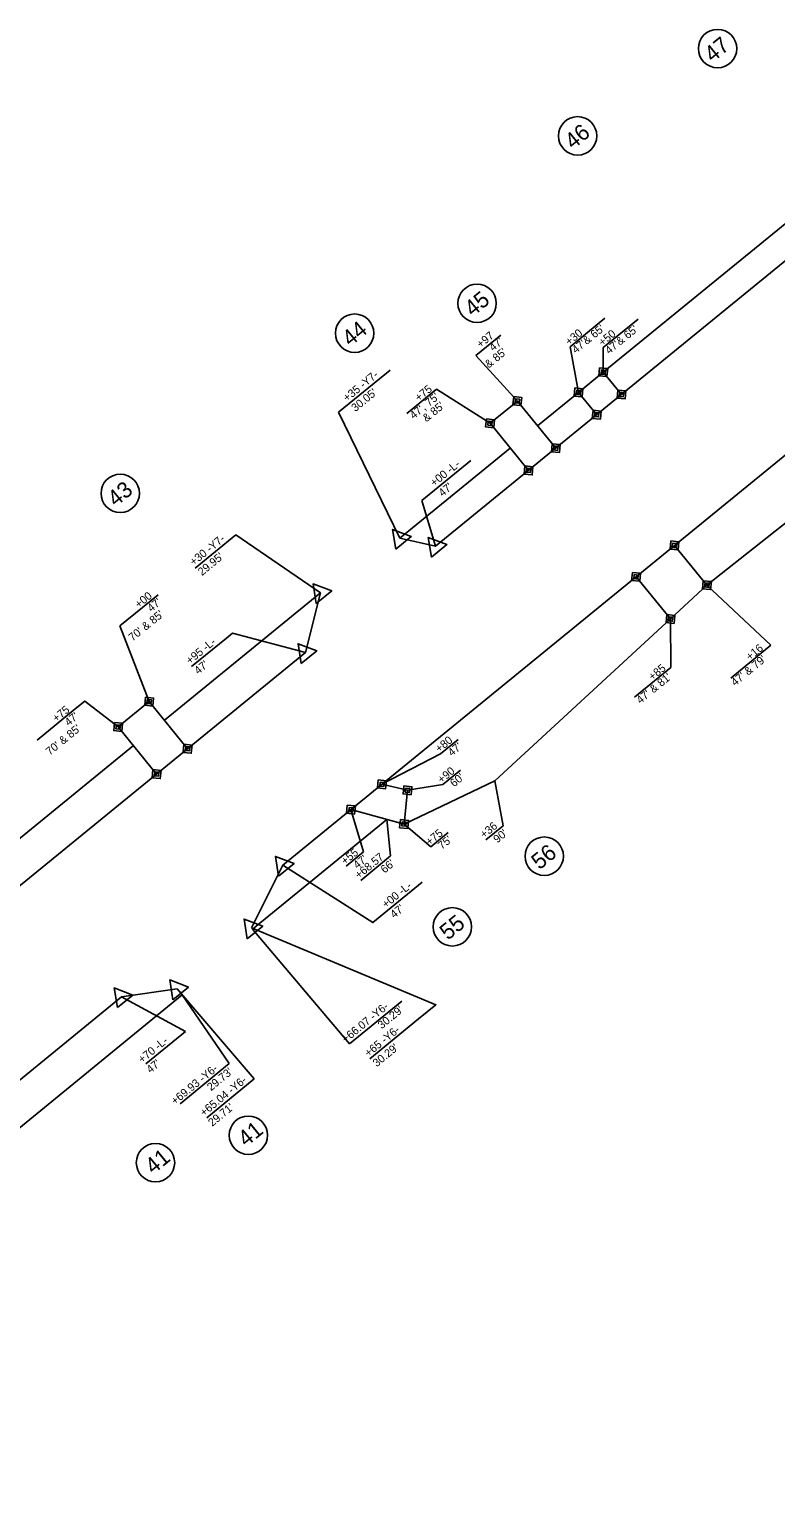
# Model space of a CAD drawing. Extents: x 2320946 to 2332748, y 597838 to 612698.
# Drawn here: x 2323481 to 2323947, y 599158 to 600075 of the extents above; entities that cross this region are included whole.
import ezdxf

# ---------------------------------------------------------------- set-up
doc = ezdxf.new("R2010")
doc.units = 0
for name, color, linetype in [('Prop Easement Construction', 7, 'Continuous'), ('Prop Easement Construction Station Offsets', 7, 'Continuous'), ('Prop Easement Permanent Drainage', 7, 'Continuous'), ('Prop Easement Permanent Drainage Station Offsets', 7, 'Continuous'), ('Prop Easement Permanent Utility', 7, 'Continuous'), ('Prop Easement Permanent Utility Station Offsets', 7, 'Continuous'), ('Prop Parcel Number CELL', 7, 'Continuous'), ('Prop ROW Marker CELL', 7, 'Continuous'), ('Prop ROW Permanent Easement CELL', 7, 'Continuous'), ('Prop ROW RW Lines', 7, 'Continuous'), ('Prop ROW Station Offsets', 7, 'Continuous')]:
    doc.layers.add(name, color=color, linetype=linetype)

msp = doc.modelspace()

# ---------------------------------------------------------------- linework, layer by layer
at = {"layer": 'Prop Easement Construction'}
for p, q in [((2323839.33, 599860.7), (2323982.64, 599977.7)), ((2323904.06, 599727.66), (2324067.08, 599856.87)), ((2323798.27, 599827.19), (2323823.84, 599848.06)), ((2323712.21, 599756.93), (2323781.23, 599813.27)), ((2323565.05, 599643.24), (2323662.58, 599722.86)), ((2323771.58, 599605.3), (2323881.31, 599706.5)), ((2323417.87, 599523.08), (2323545.68, 599627.42)), ((2323714.84, 599578.34), (2323771.58, 599605.3)), ((2323620.12, 599512.63), (2323704.17, 599581.25)), ((2323192.2, 599158.11), (2323576.17, 599471.58))]:
    msp.add_line(p, q, dxfattribs=at)
at = {"layer": 'Prop Easement Construction Station Offsets'}
for p, q in [((2323776.81, 599577.3), (2323765.91, 599568.41)), ((2323706.43, 599558.43), (2323687.77, 599543.19)), ((2323680.72, 599440.98), (2323620.12, 599512.63)), ((2323605.58, 599428.66), (2323576.17, 599471.58)), ((2323713.53, 599467.65), (2323680.72, 599440.98)), ((2323605.58, 599428.66), (2323574.96, 599403.66))]:
    msp.add_line(p, q, dxfattribs=at)
for points in [[(2323776.81, 599577.3), (2323771.58, 599605.3)], [(2323706.43, 599558.43), (2323704.17, 599581.25)]]:
    msp.add_lwpolyline(points, dxfattribs=at)
at = {"layer": 'Prop Easement Permanent Drainage'}
for p, q in [((2323823.84, 599848.06), (2323839.33, 599860.7)), ((2323850.71, 599846.76), (2323839.33, 599860.7)), ((2323835.22, 599834.11), (2323823.84, 599848.06))]:
    msp.add_line(p, q, dxfattribs=at)
at = {"layer": 'Prop Easement Permanent Drainage Station Offsets'}
for p, q in [((2323840.37, 599894.39), (2323818.55, 599876.58)), ((2323861.15, 599893.92), (2323839.33, 599876.11))]:
    msp.add_line(p, q, dxfattribs=at)
for points in [[(2323818.55, 599876.58), (2323823.84, 599848.06)], [(2323839.33, 599876.11), (2323839.33, 599860.7)]]:
    msp.add_lwpolyline(points, dxfattribs=at)
at = {"layer": 'Prop Easement Permanent Utility'}
for p, q in [((2323785.63, 599842.68), (2323768.58, 599828.77)), ((2323785.63, 599842.68), (2323809.66, 599813.24)), ((2323768.58, 599828.77), (2323792.62, 599799.33)), ((2323904.06, 599727.66), (2323883.82, 599752.44)), ((2323881.31, 599706.5), (2323859.81, 599732.84)), ((2323881.31, 599706.5), (2323904.06, 599727.66)), ((2323536.19, 599639.04), (2323555.56, 599654.85)), ((2323555.56, 599654.85), (2323579.59, 599625.42)), ((2323560.23, 599609.61), (2323536.19, 599639.04))]:
    msp.add_line(p, q, dxfattribs=at)
msp.add_lwpolyline([(2323681.64, 599587.39), (2323714.84, 599578.34), (2323716.98, 599599.45), (2323701.01, 599603.2)], dxfattribs=at)
at = {"layer": 'Prop Easement Permanent Utility Station Offsets'}
for p, q in [((2323775.21, 599883.81), (2323759.64, 599871.1)), ((2323785.63, 599842.68), (2323759.64, 599871.1)), ((2323735.13, 599850.07), (2323716.51, 599834.87)), ((2323735.13, 599850.07), (2323768.58, 599828.77)), ((2323944.08, 599690.04), (2323904.06, 599727.66)), ((2323561.09, 599721.61), (2323537.28, 599702.17)), ((2323881.58, 599676.22), (2323881.31, 599706.5)), ((2323944.08, 599690.04), (2323919.02, 599669.58)), ((2323881.58, 599676.22), (2323858.93, 599657.74)), ((2323509.36, 599650.27), (2323485.62, 599630.88)), ((2323748.61, 599631.26), (2323737.64, 599622.3)), ((2323750.01, 599611.99), (2323739.04, 599603.03)), ((2323742.42, 599572.99), (2323731.57, 599564.13)), ((2323689.56, 599560.93), (2323678.71, 599552.08))]:
    msp.add_line(p, q, dxfattribs=at)
for points in [[(2323537.28, 599702.17), (2323555.56, 599654.85)], [(2323509.36, 599650.27), (2323515.38, 599655.18), (2323536.19, 599639.04)], [(2323737.64, 599622.3), (2323701.01, 599603.2)], [(2323739.04, 599603.03), (2323716.98, 599599.45)], [(2323689.56, 599560.93), (2323681.64, 599587.39)], [(2323731.57, 599564.13), (2323714.84, 599578.34)]]:
    msp.add_lwpolyline(points, dxfattribs=at)
at = {"layer": 'Prop Parcel Number CELL'}
for p, q in [((2323910.72, 600062.92), (2323910.72, 600062.92)), ((2323823.3, 600008.37), (2323823.3, 600008.37)), ((2323760.49, 599903.76), (2323760.49, 599903.76)), ((2323683.95, 599885.07), (2323683.95, 599885.07)), ((2323537.47, 599784.98), (2323537.47, 599784.98)), ((2323802.42, 599558.29), (2323802.42, 599558.29)), ((2323745.01, 599514.15), (2323745.01, 599514.15)), ((2323617.55, 599383.94), (2323617.55, 599383.94)), ((2323559.52, 599366.78), (2323559.52, 599366.78))]:
    msp.add_line(p, q, dxfattribs=at)
for centre in [(2323910.72, 600062.92), (2323823.3, 600008.37), (2323760.49, 599903.76), (2323683.95, 599885.07), (2323537.47, 599784.98), (2323802.42, 599558.29), (2323745.01, 599514.15), (2323617.55, 599383.94), (2323559.52, 599366.78)]:
    msp.add_circle(centre, 12, dxfattribs=at)
at = {"layer": 'Prop ROW Marker CELL'}
for p, q in [((2323839.33, 599860.7), (2323839.33, 599860.7)), ((2323785.63, 599842.68), (2323785.63, 599842.68)), ((2323823.84, 599848.06), (2323823.84, 599848.06)), ((2323850.71, 599846.76), (2323850.71, 599846.76)), ((2323835.22, 599834.11), (2323835.22, 599834.11)), ((2323768.58, 599828.77), (2323768.58, 599828.77)), ((2323809.66, 599813.24), (2323809.66, 599813.24)), ((2323792.62, 599799.33), (2323792.62, 599799.33)), ((2323712.21, 599756.93), (2323712.21, 599756.93)), ((2323734.52, 599751.9), (2323734.52, 599751.9)), ((2323883.82, 599752.44), (2323883.82, 599752.44)), ((2323859.81, 599732.84), (2323859.81, 599732.84)), ((2323904.06, 599727.66), (2323904.06, 599727.66)), ((2323662.57, 599722.86), (2323662.57, 599722.86)), ((2323881.31, 599706.5), (2323881.31, 599706.5)), ((2323653.18, 599685.5), (2323653.18, 599685.5)), ((2323555.56, 599654.85), (2323555.56, 599654.85)), ((2323536.19, 599639.04), (2323536.19, 599639.04)), ((2323579.59, 599625.42), (2323579.59, 599625.42)), ((2323560.23, 599609.61), (2323560.23, 599609.61)), ((2323701.01, 599603.2), (2323701.01, 599603.2)), ((2323716.98, 599599.45), (2323716.98, 599599.45)), ((2323681.64, 599587.39), (2323681.64, 599587.39)), ((2323714.84, 599578.34), (2323714.84, 599578.34)), ((2323639.04, 599552.6), (2323639.04, 599552.6)), ((2323619.45, 599513.46), (2323619.45, 599513.46)), ((2323538.33, 599470.39), (2323538.33, 599470.39)), ((2323573.01, 599475.37), (2323573.01, 599475.37))]:
    msp.add_line(p, q, dxfattribs=at)
for points in [[(2323709.65, 599750.19), (2323707.66, 599762.51), (2323719.33, 599758.09)], [(2323731.95, 599745.16), (2323729.97, 599757.48), (2323741.64, 599753.06)], [(2323660.01, 599716.12), (2323658.02, 599728.43), (2323669.69, 599724.02)], [(2323650.62, 599678.76), (2323648.63, 599691.07), (2323660.3, 599686.66)], [(2323636.47, 599545.86), (2323634.48, 599558.18), (2323646.16, 599553.77)], [(2323616.88, 599506.72), (2323614.9, 599519.04), (2323626.57, 599514.63)], [(2323535.77, 599463.65), (2323533.78, 599475.97), (2323545.45, 599471.55)], [(2323570.44, 599468.63), (2323568.46, 599480.95), (2323580.13, 599476.54)]]:
    msp.add_lwpolyline(points, close=True, dxfattribs=at)
at = {"layer": 'Prop ROW Permanent Easement CELL'}
for points in [[(2323837.05, 599863.49), (2323842.12, 599862.98), (2323841.61, 599857.92), (2323836.54, 599858.43)], [(2323838.19, 599862.1), (2323840.72, 599861.84), (2323840.47, 599859.31), (2323837.94, 599859.57)], [(2323783.35, 599845.47), (2323788.42, 599844.96), (2323787.9, 599839.89), (2323782.84, 599840.4)], [(2323784.49, 599844.07), (2323787.02, 599843.82), (2323786.76, 599841.29), (2323784.23, 599841.54)], [(2323821.56, 599850.84), (2323826.63, 599850.33), (2323826.11, 599845.27), (2323821.05, 599845.78)], [(2323822.7, 599849.45), (2323825.23, 599849.19), (2323824.98, 599846.66), (2323822.44, 599846.92)], [(2323848.44, 599849.55), (2323853.5, 599849.04), (2323852.99, 599843.97), (2323847.93, 599844.48)], [(2323849.58, 599848.16), (2323852.11, 599847.9), (2323851.85, 599845.37), (2323849.32, 599845.62)], [(2323832.94, 599836.9), (2323838.01, 599836.39), (2323837.5, 599831.32), (2323832.43, 599831.84)], [(2323834.08, 599835.51), (2323836.62, 599835.25), (2323836.36, 599832.72), (2323833.83, 599832.97)], [(2323766.31, 599831.56), (2323771.37, 599831.04), (2323770.86, 599825.98), (2323765.8, 599826.49)], [(2323767.45, 599830.16), (2323769.98, 599829.9), (2323769.72, 599827.37), (2323767.19, 599827.63)], [(2323807.38, 599816.03), (2323812.45, 599815.52), (2323811.93, 599810.46), (2323806.87, 599810.97)], [(2323808.52, 599814.64), (2323811.05, 599814.38), (2323810.8, 599811.85), (2323808.26, 599812.11)], [(2323790.34, 599802.12), (2323795.4, 599801.61), (2323794.89, 599796.54), (2323789.83, 599797.05)], [(2323791.48, 599800.72), (2323794.01, 599800.47), (2323793.75, 599797.94), (2323791.22, 599798.19)], [(2323881.55, 599755.23), (2323886.61, 599754.72), (2323886.1, 599749.66), (2323881.03, 599750.17)], [(2323882.68, 599753.84), (2323885.22, 599753.58), (2323884.96, 599751.05), (2323882.43, 599751.31)], [(2323857.53, 599735.63), (2323862.6, 599735.12), (2323862.08, 599730.05), (2323857.02, 599730.56)], [(2323858.67, 599734.23), (2323861.2, 599733.98), (2323860.95, 599731.44), (2323858.41, 599731.7)], [(2323901.78, 599730.44), (2323906.85, 599729.93), (2323906.34, 599724.87), (2323901.27, 599725.38)], [(2323902.92, 599729.05), (2323905.45, 599728.79), (2323905.2, 599726.26), (2323902.67, 599726.52)], [(2323879.03, 599709.29), (2323884.1, 599708.78), (2323883.59, 599703.71), (2323878.52, 599704.22)], [(2323880.17, 599707.9), (2323882.71, 599707.64), (2323882.45, 599705.11), (2323879.92, 599705.36)], [(2323553.28, 599657.64), (2323558.35, 599657.13), (2323557.84, 599652.07), (2323552.77, 599652.58)], [(2323554.42, 599656.25), (2323556.95, 599655.99), (2323556.7, 599653.46), (2323554.17, 599653.72)], [(2323533.92, 599641.83), (2323538.98, 599641.32), (2323538.47, 599636.26), (2323533.41, 599636.77)], [(2323535.06, 599640.44), (2323537.59, 599640.18), (2323537.33, 599637.65), (2323534.8, 599637.91)], [(2323577.31, 599628.21), (2323582.38, 599627.69), (2323581.87, 599622.63), (2323576.8, 599623.14)], [(2323578.45, 599626.81), (2323580.99, 599626.56), (2323580.73, 599624.02), (2323578.2, 599624.28)], [(2323557.95, 599612.4), (2323563.01, 599611.88), (2323562.5, 599606.82), (2323557.44, 599607.33)], [(2323559.09, 599611), (2323561.62, 599610.75), (2323561.36, 599608.21), (2323558.83, 599608.47)], [(2323698.73, 599605.98), (2323703.8, 599605.47), (2323703.28, 599600.41), (2323698.22, 599600.92)], [(2323699.87, 599604.59), (2323702.4, 599604.33), (2323702.15, 599601.8), (2323699.61, 599602.06)], [(2323714.7, 599602.24), (2323719.77, 599601.73), (2323719.25, 599596.66), (2323714.19, 599597.17)], [(2323715.84, 599600.84), (2323718.37, 599600.59), (2323718.11, 599598.06), (2323715.58, 599598.31)], [(2323679.37, 599590.17), (2323684.43, 599589.66), (2323683.92, 599584.6), (2323678.85, 599585.11)], [(2323680.5, 599588.78), (2323683.04, 599588.52), (2323682.78, 599585.99), (2323680.25, 599586.25)], [(2323712.57, 599581.13), (2323717.63, 599580.62), (2323717.12, 599575.56), (2323712.05, 599576.07)], [(2323713.7, 599579.74), (2323716.24, 599579.48), (2323715.98, 599576.95), (2323713.45, 599577.21)]]:
    msp.add_lwpolyline(points, close=True, dxfattribs=at)
at = {"layer": 'Prop ROW RW Lines'}
for p, q in [((2323639.04, 599552.6), (2324220.01, 600026.91)), ((2323734.52, 599751.9), (2324021.13, 599985.89)), ((2323734.52, 599751.9), (2323712.21, 599756.93)), ((2323653.18, 599685.5), (2323662.58, 599722.86)), ((2323021.85, 599170.08), (2323653.18, 599685.5)), ((2323639.04, 599552.6), (2323619.45, 599513.46)), ((2323189.75, 599185.81), (2323538.33, 599470.39)), ((2323538.33, 599470.39), (2323573.08, 599475.38))]:
    msp.add_line(p, q, dxfattribs=at)
at = {"layer": 'Prop ROW Station Offsets'}
for p, q in [((2323706.07, 599861.92), (2323673.97, 599835.71)), ((2323673.97, 599835.71), (2323712.21, 599756.93)), ((2323756.58, 599805.61), (2323725.93, 599780.59)), ((2323734.52, 599751.9), (2323725.93, 599780.59)), ((2323609.78, 599759.05), (2323584.38, 599738.31)), ((2323609.78, 599759.05), (2323662.58, 599722.86)), ((2323603.81, 599694.43), (2323582.1, 599676.71)), ((2323726.25, 599542.07), (2323704.53, 599524.34)), ((2323621.28, 599419.09), (2323573.08, 599475.38)), ((2323578.23, 599448.74), (2323553.52, 599428.57)), ((2323723.87, 599456.62), (2323693.39, 599431.74)), ((2323621.28, 599419.09), (2323591.64, 599394.9))]:
    msp.add_line(p, q, dxfattribs=at)
for points in [[(2323603.81, 599694.43), (2323607.62, 599697.54), (2323653.18, 599685.5)], [(2323704.53, 599524.34), (2323695.35, 599516.84), (2323639.04, 599552.6)], [(2323723.87, 599456.62), (2323734.74, 599465.49), (2323619.45, 599513.46)], [(2323578.23, 599448.74), (2323538.33, 599470.39)]]:
    msp.add_lwpolyline(points, dxfattribs=at)

# ---------------------------------------------------------------- texts
at = {"layer": 'Prop Easement Construction Station Offsets'}
for s, p in [('+36', (2323764.84, 599569.15)), ("90'", (2323773.1, 599566.21)), ('+68.57', (2323686.61, 599543.86)), ("66'", (2323702.72, 599547.33)), ('+66.07 -Y6-', (2323678.38, 599441.38)), ("30.29'", (2323700.86, 599450.06)), ('+69.93 -Y6-', (2323571.73, 599402.64)), ("29.73'", (2323594.21, 599411.32))]:
    msp.add_text(s, height=5, rotation=39.22799, dxfattribs=at).set_placement(p)
at = {"layer": 'Prop Easement Permanent Drainage Station Offsets'}
for s, p in [("47'& 65'", (2323822.18, 599872.13)), ("47'& 65'", (2323842.96, 599871.66)), ('+30', (2323818.07, 599877.16)), ('+50', (2323838.85, 599876.69))]:
    msp.add_text(s, height=5, rotation=39.22799, dxfattribs=at).set_placement(p)
at = {"layer": 'Prop Easement Permanent Utility Station Offsets'}
for s, p in [('+97', (2323762.65, 599875.53)), ("47'", (2323770.48, 599873.53)), ("& 85'", (2323767.78, 599862.94)), ('+75', (2323724.06, 599842.15)), ("47', 75'", (2323720.83, 599831.12)), ("& 85'", (2323728.85, 599829.28)), ('+00', (2323549.11, 599712.96)), ("47'", (2323556.92, 599710.62)), ("70' & 85'", (2323545.19, 599692.33)), ('+16', (2323930.94, 599680.28)), ('+85', (2323870.06, 599667.79)), ("47' & 79'", (2323921.64, 599664.3)), ("47' & 81'", (2323862.49, 599653.21)), ('+75', (2323497.57, 599641.77)), ("70' & 85'", (2323493.5, 599621.02)), ("47'", (2323505.23, 599639.31)), ('+80', (2323736.86, 599622.79)), ("47'", (2323744.67, 599620.45)), ('+90', (2323738.26, 599603.53)), ("60'", (2323746.07, 599601.19)), ('+75', (2323730.82, 599564.65)), ("75'", (2323738.48, 599562.19)), ('+55', (2323677.96, 599552.6)), ("47'", (2323685.61, 599550.13))]:
    msp.add_text(s, height=5, rotation=39.22799, dxfattribs=at).set_placement(p)
at = {"layer": 'Prop Parcel Number CELL'}
for s, p in [('47', (2323907.58, 600053.9)), ('46', (2323820.36, 599999.51)), ('45', (2323757.68, 599895.02)), ('44', (2323681.2, 599876.37)), ('43', (2323534.67, 599776.24)), ('56', (2323799.48, 599549.43)), ('55', (2323742.2, 599505.4)), ('41', (2323616.12, 599376.32)), ('41', (2323558.09, 599359.15))]:
    msp.add_text(s, height=10, rotation=39.22799, dxfattribs=at).set_placement(p)
at = {"layer": 'Prop ROW Station Offsets'}
for s, p in [('+35 -Y7-', (2323679.23, 599842)), ("30.05'", (2323684.37, 599835.71)), ('+00 -L-', (2323733.71, 599788.93)), ("47'", (2323738.85, 599782.64)), ('+30 -Y7-', (2323583.39, 599739.52)), ("29.95'", (2323588.53, 599733.23)), ('+95 -L-', (2323581.11, 599677.92)), ("47'", (2323586.25, 599671.62)), ('+00 -L-', (2323703.54, 599525.55)), ("47'", (2323708.68, 599519.26)), ('+65 -Y6-', (2323692.65, 599432.64)), ('+70 -L-', (2323551.19, 599428.68)), ("30.29'", (2323697.79, 599426.35)), ("47'", (2323556.33, 599422.38)), ('+65.04 -Y6-', (2323589.81, 599395.42)), ("29.71'", (2323594.95, 599389.13))]:
    msp.add_text(s, height=5, rotation=39.22799, dxfattribs=at).set_placement(p)

doc.saveas('drawing.dxf')
